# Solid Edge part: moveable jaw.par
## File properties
Title: Moveable Jaw
Author: Robert a Rhodes jr
Template: Normal.par
Last saved by: CADCIM
Revision: 16
Application: Solid Edge
Accuracy: 0.99
Material: iron
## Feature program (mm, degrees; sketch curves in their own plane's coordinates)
sketch for "unnamed Protrusion 1" plane through (0, 0, 0) normal (0, -1, 0) x-axis (1, 0, 0)
  line (-36.5256, 25.2528) -> (-36.5256, -34.7472)
  line (-36.5256, -34.7472) -> (-33.0256, -34.7472)
  line (-33.0256, -34.7472) -> (-33.0256, -32.2472)
  line (-33.0256, -32.2472) -> (-30.5256, -32.2472)
  line (-30.5256, -32.2472) -> (-30.5256, -29.7472)
  line (-30.5256, -29.7472) -> (-28.0256, -29.7472)
  line (-28.0256, -29.7472) -> (-28.0256, -27.2472)
  line (-28.0256, -27.2472) -> (-25.5256, -27.2472)
  line (-25.5256, -27.2472) -> (-25.5256, -24.7472)
  line (-25.5256, -24.7472) -> (-23.0256, -24.7472)
  line (-23.0256, -24.7472) -> (-23.0256, -22.2472)
  line (-23.0256, -22.2472) -> (-20.5256, -22.2472)
  line (-20.5256, -22.2472) -> (-20.5256, -19.7472)
  line (-20.5256, -19.7472) -> (-18.0256, -19.7472)
  line (-18.0256, -22.2472) -> (-18.0256, -19.7472)
  line (-15.5256, -22.2472) -> (-18.0256, -22.2472)
  line (-15.5256, -24.7472) -> (-15.5256, -22.2472)
  line (-13.0256, -24.7472) -> (-15.5256, -24.7472)
  line (-13.0256, -27.2472) -> (-13.0256, -24.7472)
  line (-10.5256, -27.2472) -> (-13.0256, -27.2472)
  line (-10.5256, -29.7472) -> (-10.5256, -27.2472)
  line (-8.0256, -29.7472) -> (-10.5256, -29.7472)
  line (-8.0256, -32.2472) -> (-8.0256, -29.7472)
  line (-5.5256, -32.2472) -> (-8.0256, -32.2472)
  line (-5.5256, -34.7472) -> (-5.5256, -32.2472)
  line (-2.0256, -34.7472) -> (-5.5256, -34.7472)
  line (-2.0256, -34.7472) -> (-2.0256, 25.2528)
  line (-2.0256, 25.2528) -> (-36.5256, 25.2528)
extrude "unnamed Protrusion 1" add finite 18 along -normal
sketch for "Hole_1" plane through (-19.2756, 9, 25.2528) normal (0, 0, 1) x-axis (1, 0, 0)
  hole centre (0, 0) bore radius 6
hole "Hole_1" diameter 12 finite  VBottomAngle = 118 deg
sketch for "Hole_2" plane through (-2.0256, 9, -4.7472) normal (1, 0, 0) x-axis (0, 1, 0)
  hole centre (0, 23) bore radius 4.5
hole "Hole_2" diameter 9 through
chamfer "Chamfer_1" setback 2
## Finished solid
Body 1: solid body, 38 faces, 98 edges, 60 vertices.
  Faces by surface: plane 34, cylinder 3, cone 1
  Edges by curve: line 92, circle 4, intersection 2
Bounding box of the edges (mm): 34.500 x 18.000 x 60.000, from (-36.5256, 0, -34.7472) to (-2.0256, 18, 25.2528).
Cylindrical faces by radius (mm): R4.5 x2, R6 x1
Conical faces (half-angle, radius in mm at the cone's reference point): 59 deg R6 x1
Planar faces by outward normal: +x 7, +y 1, +z 1, -x 7, -y 1, -z 13, oblique 4
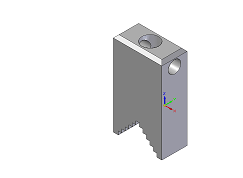
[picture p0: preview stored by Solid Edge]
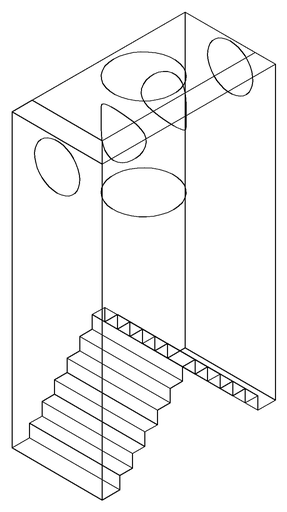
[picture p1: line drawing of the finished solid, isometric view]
